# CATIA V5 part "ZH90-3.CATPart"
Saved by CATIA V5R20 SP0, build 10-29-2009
Part number: ZH903
Bounding box of the stored display mesh (mm): x 0 to 309, y -20 to 55, z -29.7 to 15
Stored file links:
  C:\Users\Utente\Desktop\IO LAVORO\3D X SITO CF\X SITO\PLASTICA\ZH90\ZH90-3.CATPart
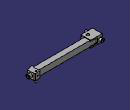
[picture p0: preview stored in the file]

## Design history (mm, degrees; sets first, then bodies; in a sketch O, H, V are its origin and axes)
Set1
  DatumSurface1 to DatumSurface16 "_ZH90/3_head"
  DatumSurface17 to DatumSurface34 "_ZH90/3_screw1"
  DatumSurface35 to DatumSurface55 "_ZH90/3_hand"
  DatumSurface56 to DatumSurface73 "_ZH90/3_screw2"
  DatumSurface74 to DatumSurface94 "_ZH90/3_he"
  DatumSurface95 to DatumSurface109 "_ZH90/3_screw3"
  DatumSurface110 to DatumSurface117 "_ZH90/3_stift1"
  DatumSurface118 to DatumSurface127 "_ZH90/3_stift2"
Body1 (main body)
